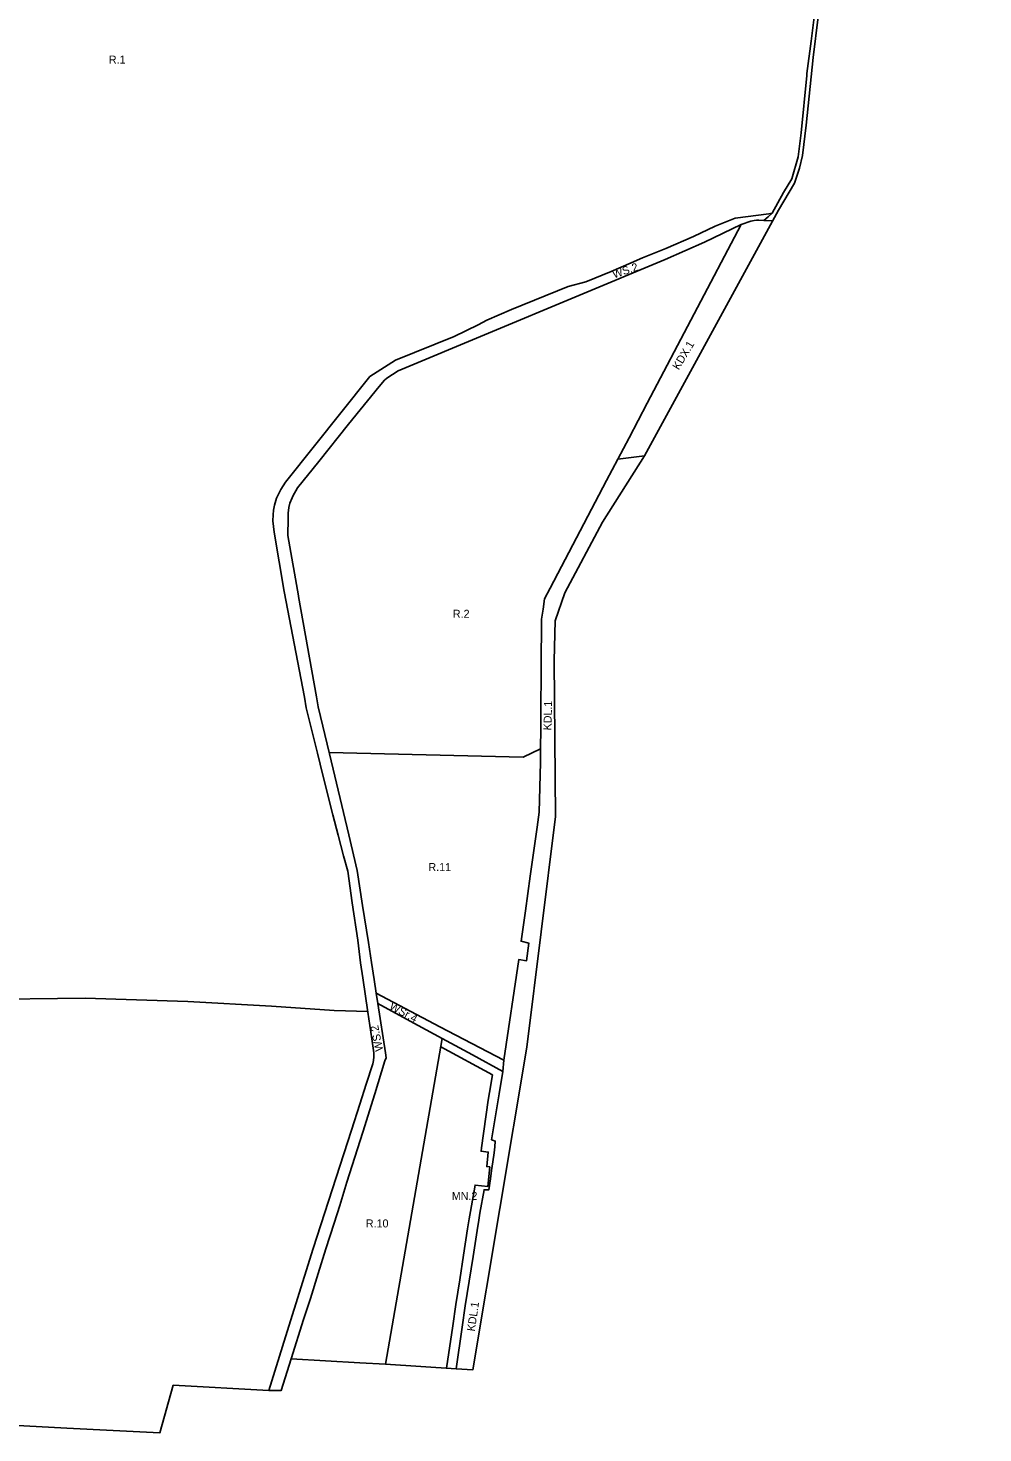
# Model space of a CAD drawing. Extents: x 7418237 to 7420198, y 5543414 to 5545133.
# Drawn here: x 7419412 to 7420008, y 5543414 to 5544292 of the extents above; entities that cross this region are included whole.
import ezdxf

# ---------------------------------------------------------------- set-up
doc = ezdxf.new("R2010")
doc.units = 0
for name, color, linetype in [('linie rozgraniczające', 7, 'Continuous'), ('nieprzekraczalne linie zabudowy', 7, 'Continuous'), ('przeznaczenia terenów', 7, 'Continuous')]:
    doc.layers.add(name, color=color, linetype=linetype)

msp = doc.modelspace()

# ---------------------------------------------------------------- linework, layer by layer
at = {"layer": 'linie rozgraniczające'}
for p, q in [((7419770.48, 5543982.87), (7419796.88, 5544024.41)), ((7419747.05, 5543938.75), (7419770.48, 5543982.87)), ((7419740.93, 5543921.36), (7419747.05, 5543938.75)), ((7419723.31, 5543654.82), (7419741.23, 5543798.97)), ((7419634.92, 5543456.76), (7419670.42, 5543660.3))]:
    msp.add_line(p, q, dxfattribs=at)
for points in [[(7419796.88, 5544024.41), (7419880.5, 5544177.97), (7419890.57, 5544194.91), (7419893.75, 5544204.23), (7419895.58, 5544212.12), (7419897.77, 5544231.17), (7419902.12, 5544273.29), (7419905.34, 5544298.82), (7419906.29, 5544305.28), (7419908.63, 5544314.85), (7419912.35, 5544326.62), (7419917.38, 5544336.85), (7419921.73, 5544343.62), (7419942.3, 5544369.78), (7419952.58, 5544381.37), (7419959.87, 5544389.22), (7419969.6, 5544395.68), (7419987.34, 5544401.57), (7420008.22, 5544408.46)], [(7419876.63, 5544176.05), (7419883.58, 5544188.94), (7419888.77, 5544197.49), (7419892.78, 5544211.37), (7419894.69, 5544226.34), (7419898.17, 5544262.21), (7419898.33, 5544263.46), (7419900.88, 5544283.58), (7419903.27, 5544301.85), (7419906.46, 5544316.97), (7419910.22, 5544328.04), (7419914.99, 5544337.49), (7419916.87, 5544342.11), (7419919.47, 5544344.16), (7419928.84, 5544357.02), (7419941.68, 5544373.89), (7419956.87, 5544391.47), (7419970.61, 5544399.87)], [(7419625.12, 5544074), (7419641.22, 5544084.17), (7419677.84, 5544099.09), (7419692.97, 5544106.25), (7419698.3, 5544109.28), (7419713.74, 5544115.83), (7419749.08, 5544130.17), (7419760.09, 5544133.18), (7419775.96, 5544139.65), (7419788.42, 5544144.98), (7419795.49, 5544148.16), (7419810.05, 5544154.04), (7419827.52, 5544161.43), (7419840.95, 5544167.93), (7419853.52, 5544172.93), (7419874.41, 5544175.75), (7419876.63, 5544176.05)], [(7419876.63, 5544176.05), (7419874.02, 5544173.79), (7419871.4, 5544171.52)], [(7419857.17, 5544169.03), (7419834.32, 5544157.91), (7419809.74, 5544147.08), (7419642.85, 5544077.59), (7419635.81, 5544072.9), (7419634.37, 5544071.68), (7419630.97, 5544067.67)], [(7419701.32, 5543596.91), (7419705.16, 5543620.69), (7419706, 5543625.65), (7419708.37, 5543639.71), (7419708.87, 5543646.71), (7419718.36, 5543709.68), (7419723.14, 5543708.93), (7419724.59, 5543719.83), (7419719.75, 5543721.04), (7419722.42, 5543740), (7419725.47, 5543761.65), (7419729.67, 5543792.43), (7419730.95, 5543801.78), (7419731.75, 5543832.87), (7419732.52, 5543922.41), (7419733.54, 5543928.67), (7419734.35, 5543935), (7419737.78, 5543941.81), (7419773.09, 5544009.04), (7419787.27, 5544035.72), (7419798.5, 5544057.37), (7419857.17, 5544169.03), (7419863.32, 5544171.1), (7419865.3, 5544171.46), (7419866.71, 5544171.66), (7419868.29, 5544171.74), (7419871.4, 5544171.52), (7419876.9, 5544171.37)], [(7419562.04, 5543440.36), (7419572.51, 5543473.82), (7419589.78, 5543529.04), (7419613.7, 5543603.06), (7419618.96, 5543619.29), (7419622.84, 5543631.82), (7419627.02, 5543644.39), (7419627.45, 5543646.48), (7419627.69, 5543648.82), (7419627.71, 5543651.31), (7419626.45, 5543660.08), (7419624.06, 5543676.7), (7419620.84, 5543698.25), (7419619.44, 5543707.65), (7419617.71, 5543721.82), (7419614.26, 5543745.11), (7419611.45, 5543764.97), (7419608.86, 5543774.5), (7419605.5, 5543787.39), (7419602.19, 5543800.06), (7419595.89, 5543824.9), (7419592.5, 5543838.7), (7419585.43, 5543866.84), (7419584.31, 5543873.63), (7419571.69, 5543939.72), (7419565.35, 5543976.75), (7419564.65, 5543983.9), (7419564.78, 5543987.65), (7419565.11, 5543990.38), (7419565.61, 5543993.53), (7419566.95, 5543998), (7419569.59, 5544003.29), (7419572.61, 5544007.97), (7419625.12, 5544074)], [(7419630.97, 5544067.67), (7419611.85, 5544044.14), (7419593.26, 5544020.97), (7419579.93, 5544004.35), (7419577.2, 5543999.28), (7419576.76, 5543998.11), (7419575.23, 5543994.93), (7419574.64, 5543992.19), (7419574.21, 5543988.63), (7419574.14, 5543985.23), (7419573.99, 5543974.54), (7419580.57, 5543936.94), (7419580.64, 5543936.56), (7419591.98, 5543873.85), (7419593.01, 5543867.67), (7419600.06, 5543838.1), (7419612.04, 5543787.65), (7419617.38, 5543765.22), (7419620.73, 5543743.37), (7419624.28, 5543720.3), (7419626.22, 5543707.72), (7419627.84, 5543697.17), (7419629.16, 5543688.57), (7419630.21, 5543682.12), (7419634.96, 5543651.41), (7419635.39, 5543648.23), (7419634.49, 5543646.32), (7419628.37, 5543625.78), (7419620.82, 5543601.72), (7419610.83, 5543570.57), (7419606.41, 5543555.95), (7419602.84, 5543544.91), (7419597.66, 5543528.85), (7419592.91, 5543513.51), (7419588.07, 5543497.87), (7419583.85, 5543484.74), (7419576.1, 5543460.03)], [(7419796.88, 5544024.41), (7419788.53, 5544023.4), (7419780.18, 5544022.38)], [(7419741.23, 5543798.97), (7419740.45, 5543896.53), (7419740.93, 5543921.36)], [(7419731.82, 5543841.39), (7419721.03, 5543836.19), (7419599.82, 5543839.11)], [(7419623.98, 5543677.25), (7419602.88, 5543677.82), (7419563.86, 5543680.45), (7419511.5, 5543683.44), (7419447.35, 5543685.48), (7419378.15, 5543684.6), (7419245.84, 5543722.18), (7419222.11, 5543732.59), (7419212.8, 5543737.84)], [(7419629.16, 5543688.57), (7419669.02, 5543667.64), (7419708.87, 5543646.71)], [(7419708.37, 5543639.71), (7419689.4, 5543650), (7419670.42, 5543660.3), (7419650.32, 5543671.21), (7419630.21, 5543682.12)], [(7419634.92, 5543456.76), (7419679.17, 5543453.95), (7419689.57, 5543453.29), (7419723.31, 5543654.82)], [(7419701.28, 5543577.75), (7419702.1, 5543583.31), (7419702.92, 5543588.87), (7419703.27, 5543592.54), (7419703.61, 5543596.22), (7419702.46, 5543596.57), (7419701.32, 5543596.91)], [(7419679.17, 5543453.95), (7419682.93, 5543479.84), (7419684.8, 5543493.23), (7419687.32, 5543508.63), (7419689.69, 5543524), (7419692.21, 5543540.35), (7419693.25, 5543546.69), (7419693.97, 5543551.15), (7419696.58, 5543565.76), (7419699.46, 5543565.67), (7419700.62, 5543572.5), (7419701.28, 5543577.75)], [(7419377.93, 5543419.99), (7419435.83, 5543416.82), (7419464.86, 5543415.32), (7419493.98, 5543413.82), (7419502.4, 5543443.63), (7419562.04, 5543440.36), (7419569.87, 5543440.35), (7419576.1, 5543460.03), (7419619.03, 5543457.64), (7419634.92, 5543456.76)]]:
    msp.add_lwpolyline(points, dxfattribs=at)
at = {"layer": 'nieprzekraczalne linie zabudowy'}
msp.add_lwpolyline([(7419673.16, 5543454.33), (7419676.99, 5543480.69), (7419678.87, 5543494.13), (7419681.39, 5543509.57), (7419683.76, 5543524.91), (7419686.28, 5543541.29), (7419687.33, 5543547.65), (7419688.05, 5543552.16), (7419691, 5543568.65), (7419698.85, 5543567.87), (7419700.11, 5543580.02), (7419698.21, 5543580.23), (7419699.23, 5543589.34), (7419694.75, 5543589.84), (7419694.99, 5543592.02), (7419699.24, 5543621.67), (7419700.08, 5543626.65), (7419701.92, 5543637.52), (7419669.51, 5543655.1)], dxfattribs=at)

# ---------------------------------------------------------------- texts
at = {"layer": 'przeznaczenia terenów'}
for s, p in [('R.1', (7419462.19, 5544269.54)), ('R.2', (7419677.11, 5543923.21)), ('R.11', (7419661.84, 5543764.93)), ('MN.2', (7419676.42, 5543559.45)), ('R.10', (7419622.75, 5543542.23))]:
    msp.add_text(s, height=5, dxfattribs=at).set_placement(p)
for s, rotation, p in [('WS.2', 18.34196, (7419777.81, 5544135.29)), ('KDX.1', 58.90631, (7419818.18, 5544077.74)), ('KDL.1', 88.67226, (7419738.65, 5543852.8)), ('WSr.4', 331.61628, (7419636.97, 5543678.89)), ('WS.2', 101.3006, (7419633.58, 5543652.87)), ('KDL.1', 81.5832, (7419690.78, 5543477.02))]:
    msp.add_text(s, height=5, rotation=rotation, dxfattribs=at).set_placement(p)

doc.saveas('drawing.dxf')
